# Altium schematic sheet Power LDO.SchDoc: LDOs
size 431 x 279 mm; Date: Not shown in title block; ApprovedBy: Not shown in title block; CheckedBy: Not shown in title block; Author: Not shown in title block; CompanyName: Not shown in title block; Engineer: Not shown in title block; Organization: Not shown in title block; Address1: Not shown in title block; Address2: Not shown in title block; Address3: Not shown in title block; Address4: Not shown in title block; DocumentNumber: 1; Revision: Use project parameter SCH_Rev; SheetNumber: 4; SheetTotal: 15; PageSetup: Record=PageOptions¦CenterHorizontal=True¦CenterVertical=True¦PrintScale=1.00¦XCorrection=1.00¦YCorrection=1.00¦PrintKind=0¦BorderSize=5000000¦LeftOffset=0¦BottomOffset=0¦Orientation=2¦PaperLength=1000¦PaperWidth=1000¦Scale=100¦PaperSource=15¦PrintQuality=600¦MediaType=1¦DitherType=10¦PaperKind=Letter¦PrintScaleMode=1
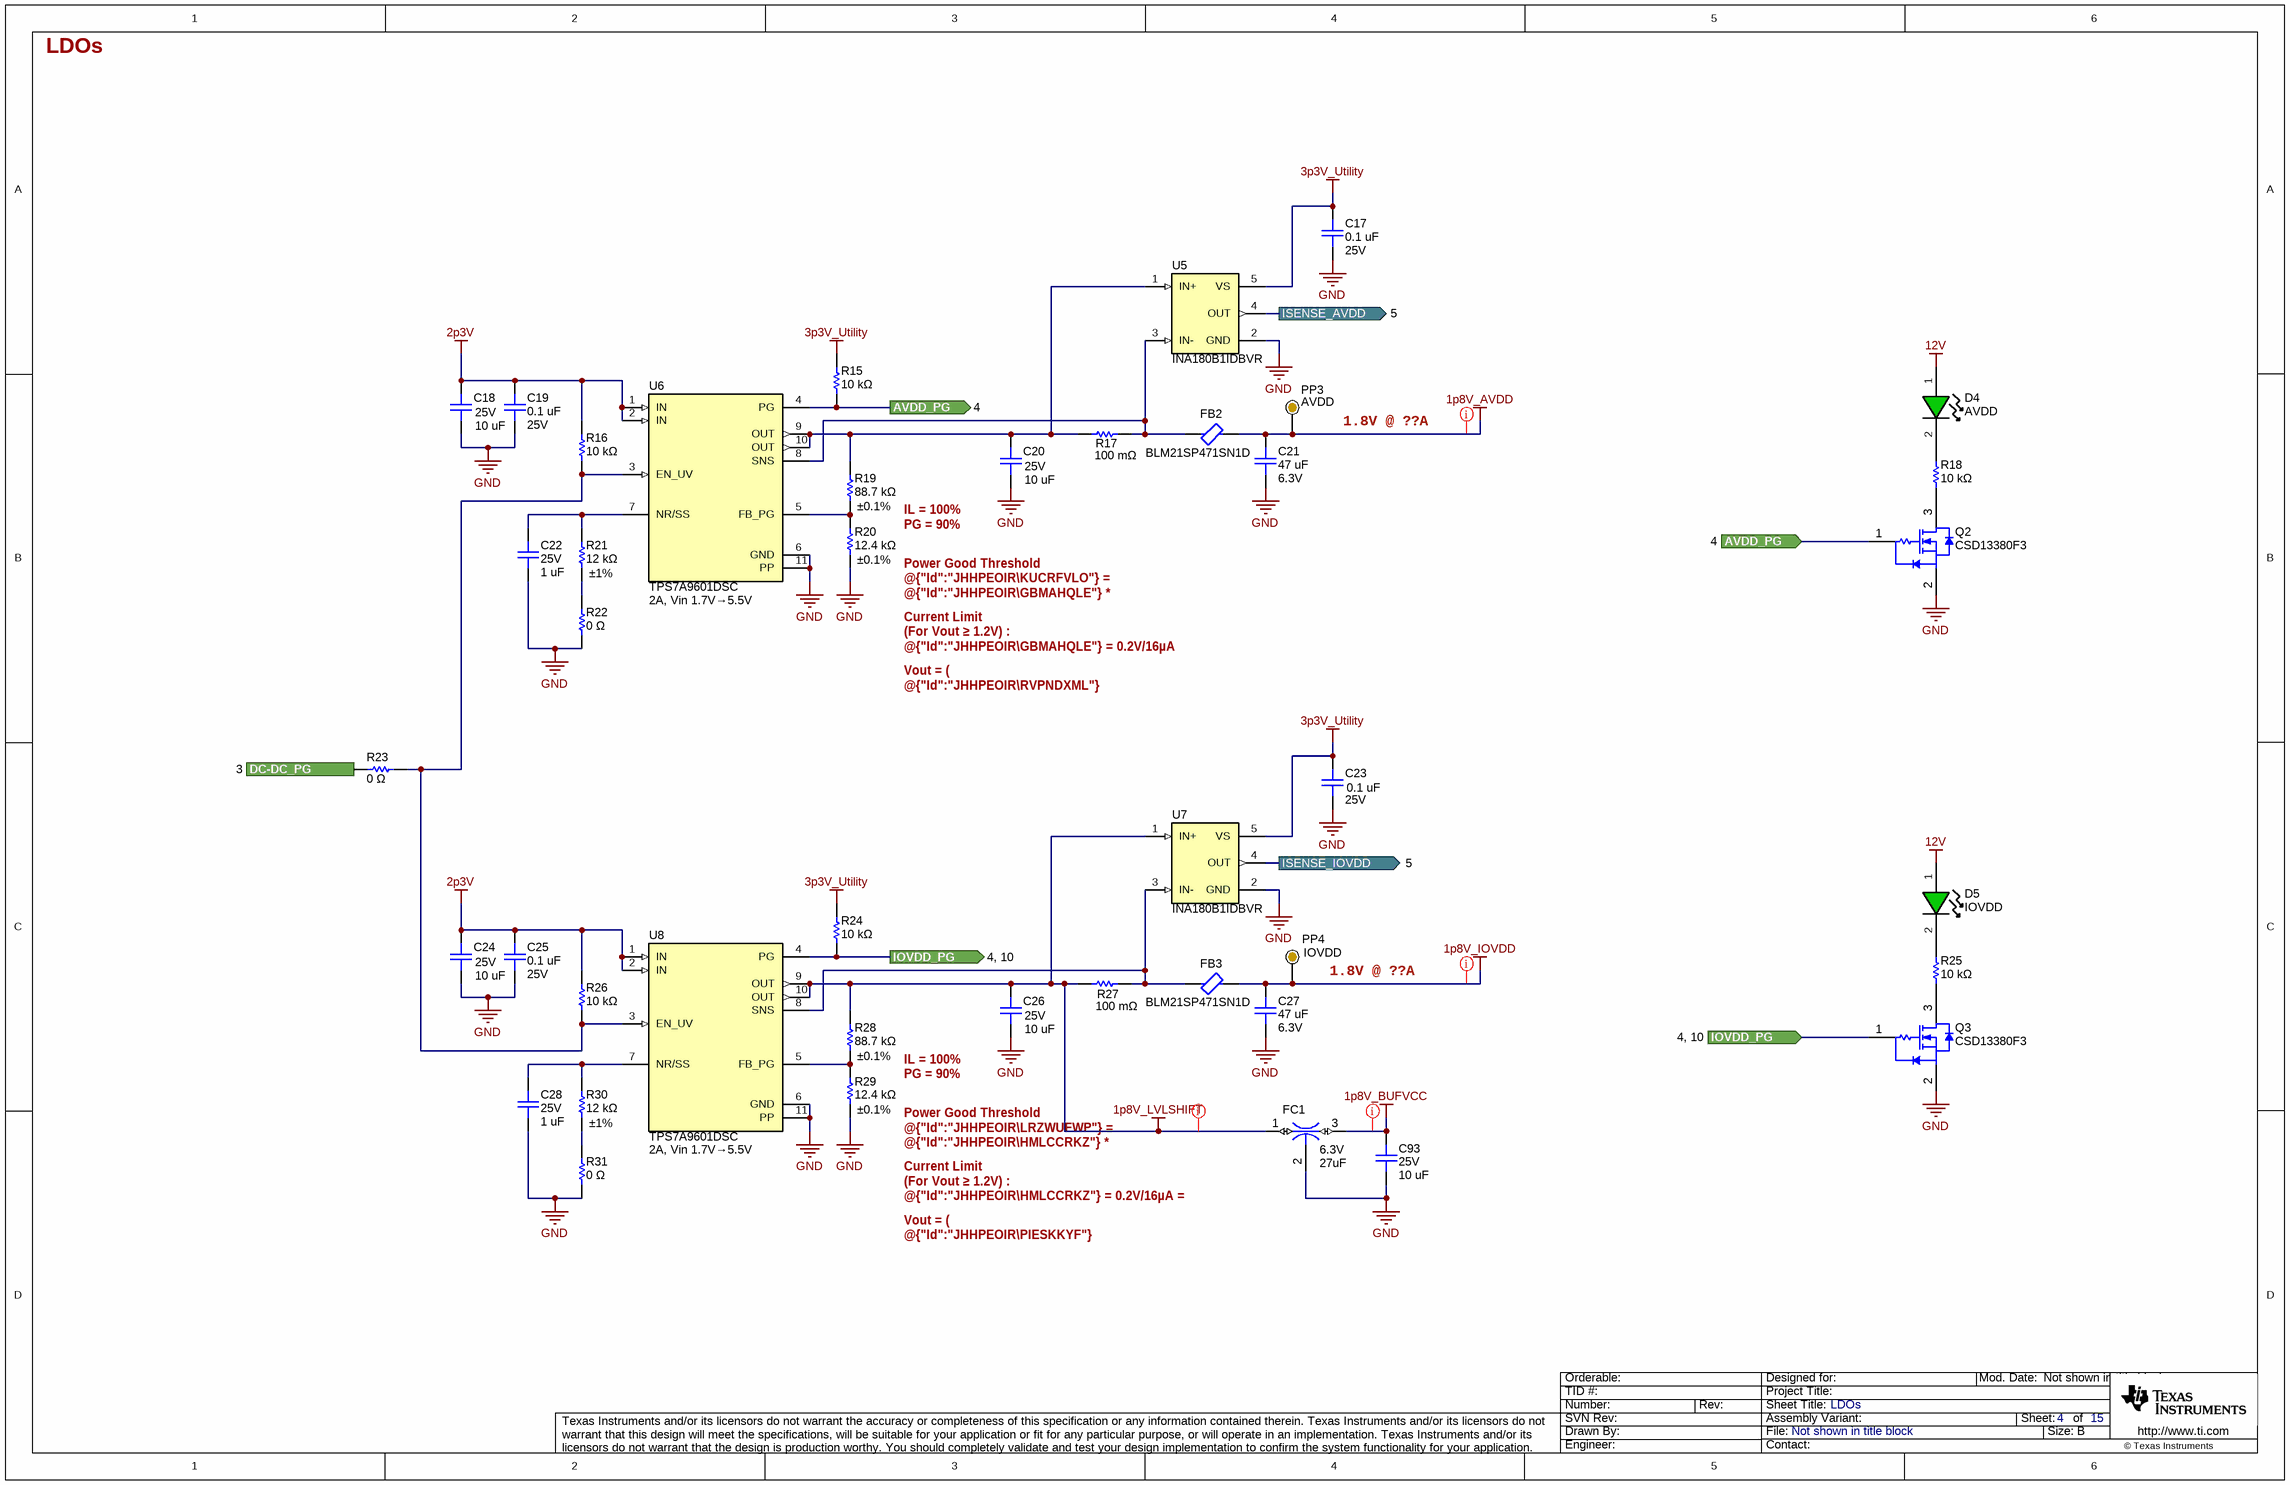
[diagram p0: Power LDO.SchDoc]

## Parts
C17  value 0.1 uF  Voltage - Rated: 25V  [0402L_cap]  (hidden comment: GRT155R71E104KE01J)
C18  value 10 uF  Voltage - Rated: 25V  [0805L_cap]  (hidden comment: C2012X7S1E106K125AC)
C19  value 0.1 uF  Voltage - Rated: 25V  [0402L_cap]  (hidden comment: GRT155R71E104KE01J)
C20  value 10 uF  Voltage - Rated: 25V  [0805L_cap]  (hidden comment: C2012X7S1E106K125AC)
C21  value 47 uF  Voltage - Rated: 6.3V  [0603L_cap]  (hidden comment: GRM188R60J476ME15D)
C22  value 1 uF  Voltage - Rated: 25V  [0402L_cap]  (hidden comment: C1005X5R1E105K050BC)
C23  value 0.1 uF  Voltage - Rated: 25V  [0402L_cap]  (hidden comment: GRT155R71E104KE01J)
C24  value 10 uF  Voltage - Rated: 25V  [0805L_cap]  (hidden comment: C2012X7S1E106K125AC)
C25  value 0.1 uF  Voltage - Rated: 25V  [0402L_cap]  (hidden comment: GRT155R71E104KE01J)
C26  value 10 uF  Voltage - Rated: 25V  [0805L_cap]  (hidden comment: C2012X7S1E106K125AC)
C27  value 47 uF  Voltage - Rated: 6.3V  [0603L_cap]  (hidden comment: GRM188R60J476ME15D)
C28  value 1 uF  Voltage - Rated: 25V  [0402L_cap]  (hidden comment: C1005X5R1E105K050BC)
C93  value 10 uF  Voltage - Rated: 25V  [0603L_cap]  (hidden comment: GRM188R61E106KA73J)
D4  Text1: AVDD  [LED_LTST-C190-Green]  (hidden comment: LTST-C191TGKT)
D5  Text1: IOVDD  [LED_LTST-C190-Green]  (hidden comment: LTST-C191TGKT)
FB2  BLM21SP471SN1D  [0805L]
FB3  BLM21SP471SN1D  [0805L]
FC1  value 27uF  Voltage - Rated: 6.3V  [NFM31PC]  (hidden comment: dcp00001)
PP3  Text1: AVDD  [ProbePoint_TH_40mil]  (hidden comment: Probe Point)  (no BOM)
PP4  Text1: IOVDD  [ProbePoint_TH_40mil]  (hidden comment: Probe Point)  (no BOM)
Q2  CSD13380F3  [YJM0003A]
Q3  CSD13380F3  [YJM0003A]
R15  value 10 kΩ  [0402L]  (hidden comment: ERA-2AEB103X)
R16  value 10 kΩ  [0402L]  (hidden comment: ERJ-2RKF1002X)
R17  value 100 mΩ  [CCS0603FLxLxx]  (hidden comment: WSLP0603R1000FEA)
R18  value 10 kΩ  [0805L]  (hidden comment: ERJ-HP6F1002V)
R19  value 88.7 kΩ  Tolerance: ±0.1%  [0402L]  (hidden comment: RT0402BRD0788K7L)
R20  value 12.4 kΩ  Tolerance: ±0.1%  [0402L]  (hidden comment: ERA-2AEB1242X)
R21  value 12 kΩ  Tolerance: ±1%  [0402L]  (hidden comment: ERJ-2RKF1202X)
R22  value 0 Ω  [0402L]  (hidden comment: ERJ-U020R00X)
R23  value 0 Ω  [0402L]  (hidden comment: ERJ-U020R00X)
R24  value 10 kΩ  [0402L]  (hidden comment: ERA-2AEB103X)
R25  value 10 kΩ  [0805L]  (hidden comment: ERJ-HP6F1002V)
R26  value 10 kΩ  [0402L]  (hidden comment: ERJ-2RKF1002X)
R27  value 100 mΩ  [CCS0603FLxLxx]  (hidden comment: WSLP0603R1000FEA)
R28  value 88.7 kΩ  Tolerance: ±0.1%  [0402L]  (hidden comment: RT0402BRD0788K7L)
R29  value 12.4 kΩ  Tolerance: ±0.1%  [0402L]  (hidden comment: ERA-2AEB1242X)
R30  value 12 kΩ  Tolerance: ±1%  [0402L]  (hidden comment: ERJ-2RKF1202X)
R31  value 0 Ω  [0402L]  (hidden comment: ERJ-U020R00X)
U5  INA180B1IDBVR  [DBV0005A]
U6  TPS7A9601DSC  Text1: 2A, Vin 1.7V→5.5V  [DRC0010J]
U7  INA180B1IDBVR  [DBV0005A]
U8  TPS7A9601DSC  Text1: 2A, Vin 1.7V→5.5V  [DRC0010J]

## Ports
AVDD_PG (in, see 4), AVDD_PG (out, see 4), DC-DC_PG (in, see 3), IOVDD_PG (in, see 4, 10), IOVDD_PG (out, see 4, 10), ISENSE_AVDD (out, see 5), ISENSE_IOVDD (out, see 5)

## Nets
1p8V_AVDD: C21.2 FB2.2 PP3.1
1p8V_BUFVCC: C93.2 FC1.3
1p8V_IOVDD: C27.2 FB3.2 PP4.1
1p8V_LVLSHIFT: C26.2 FC1.1 R27.1 R28.2 U7.1(IN+) U8.9(OUT) U8.10(OUT)
2p3V: C18.2 C19.2 C24.2 C25.2 R16.2 R26.2 U6.1(IN) U6.2(IN) U8.1(IN) U8.2(IN)
3p3V_Utility: C17.2 C23.2 R15.2 R24.2 U5.5(VS) U7.5(VS)
12V: D4.1(A) D5.1(A)
GND: C17.1 C18.1 C19.1 C20.1 C21.1 C22.1 C23.1 C24.1 C25.1 C26.1 C27.1 C28.1 C93.1 FC1.2 Q2.2(S) Q3.2(S) R20.1 R22.1 R29.1 R31.1 U5.2(GND) U6.6(GND) U6.11(PP) U7.2(GND) U8.6(GND) U8.11(PP)
AVDD_PG: Q2.1(G) R15.1 U6.4(PG) ; port AVDD_PG
DC-DC_PG: R23.2 ; port DC-DC_PG
IOVDD_PG: Q3.1(G) R24.1 U8.4(PG) ; port IOVDD_PG
ISENSE_AVDD: U5.4(OUT) ; port ISENSE_AVDD
ISENSE_IOVDD: U7.4(OUT) ; port ISENSE_IOVDD
NetC20_2: C20.2 R17.1 R19.2 U5.1(IN+) U6.9(OUT) U6.10(OUT)
NetC22_2: C22.2 R21.2 U6.7(NR/SS)
NetC28_2: C28.2 R30.2 U8.7(NR/SS)
NetD4_2: D4.2(K) R18.2
NetD5_2: D5.2(K) R25.2
NetFB2_1: FB2.1 R17.2 U5.3(IN-) U6.8(SNS)
NetFB3_1: FB3.1 R27.2 U7.3(IN-) U8.8(SNS)
NetQ2_3: Q2.3(D) R18.1
NetQ3_3: Q3.3(D) R25.1
NetR16_1: R16.1 R23.1 R26.1 U6.3(EN_UV) U8.3(EN_UV)
NetR19_1: R19.1 R20.2 U6.5(FB_PG)
NetR21_1: R21.1 R22.2
NetR28_1: R28.1 R29.2 U8.5(FB_PG)
NetR30_1: R30.1 R31.2

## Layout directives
net class Power; net class DUTPwr: 1p8V_AVDD, 1p8V_IOVDD
net class Power; net class GenPwr: 1p8V_BUFVCC, 1p8V_LVLSHIFT

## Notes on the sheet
- 1.8V @ ??A
- IL = 100%
  PG = 90%
- Power Good Threshold
  @{"Id":"JHHPEOIR\KUCRFVLO"} = @{"Id":"JHHPEOIR\GBMAHQLE"} * (VOUT/0.2*K-1)
  K = PG % Threshold
- Current Limit
  (For Vout ≥ 1.2V) : @{"Id":"JHHPEOIR\GBMAHQLE"} = 0.2V/16µA = 12.4k
- Vout = ( @{"Id":"JHHPEOIR\RVPNDXML"} + @{"Id":"JHHPEOIR\VYCEATNQ"} ) *150µA
  Vout = 1.8V
- (near PP4) 1.8V @ ??A
- Power Good Threshold
  @{"Id":"JHHPEOIR\LRZWUFWP"} = @{"Id":"JHHPEOIR\HMLCCRKZ"} * (VOUT/0.2*K-1)
  K = PG % Threshold
- Current Limit
  (For Vout ≥ 1.2V) : @{"Id":"JHHPEOIR\HMLCCRKZ"} = 0.2V/16µA = 12.4k
- Vout = ( @{"Id":"JHHPEOIR\PIESKKYF"} + @{"Id":"JHHPEOIR\BNWUTHKX"} ) *150µA
  Vout = 1.8V

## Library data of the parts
C17 C19 C23 C25 = capcc09401: CAP CER 0.1UF 25V X7R 0402; Manufacturer: Murata; CompType: Capacitor Ceramic; Tolerance: ±10%; SizeX_mm: 1; SizeY_mm: 0.5; SizeZ_mm: 0.7
C18 C20 C24 C26 = capcc03511: CAP CER 10UF 25V X7S 0805; Manufacturer: TDK Corporation; CompType: Capacitor Ceramic; Tolerance: ±10%; SizeX_mm: 2; SizeY_mm: 1.25; SizeZ_mm: 1.5
C21 C27 = GRM188R60J476ME15D: CAP CER 47UF 6.3V X5R 0603; Manufacturer: Murata; CompType: Capacitor Ceramic; Tolerance: ±20%; SizeX_mm: 1.6; SizeY_mm: 0.81; SizeZ_mm: 0.9
C22 C28 = capcc02750: CAP CER 1UF 25V X5R 0402; Manufacturer: TDK Corporation; CompType: Capacitor Ceramic; Tolerance: ±10%; SizeX_mm: 1; SizeY_mm: 0.5; SizeZ_mm: 0.55
C93 = capcc09400: CAP CER 10UF 25V X5R 0603; Manufacturer: Murata; CompType: Capacitor Ceramic; Tolerance: ±10%; SizeX_mm: 1.6; SizeY_mm: 0.8; SizeZ_mm: 1
D4 D5 = cmp00247: LED GREEN CLEAR CHIP SMD; Manufacturer: Lite-On Inc.; Current Rating (Amps): 20mA; Voltage - Forward (Vf) (Typ): 3.2V; SizeX_mm: 1.6; SizeY_mm: 0.8; SizeZ_mm: 0.65
FB2 FB3 = dcp00579: FERRITEBEAD SMD Z100MHZ=470OHM 2; Manufacturer: Murata Electronics; Current: 2.5A; Impedance: 470 Ω
FC1 = dcp00001: Feed through capactior 27uF; PartNumber: NFM31PC276B0J3L; Manufacturer: Murata; CompType: Feed Thru Cap; Tolerance: ±20%; SizeX_mm: 3.2; SizeY_mm: 1.6; SizeZ_mm: 1.5; Current: 6A; DCR: 5 mΩ
PP3 PP4 = Probe Point: Probe Point that can be used in lue of a test point; UniqueID: cmp00025
Q2 Q3 = CSD13380F3: MOSFET, N-CH, 12 V, 3.6 A, YJM0003A (PICOSTAR-3); Manufacturer: Texas Instruments; CompType: NMOS
R15 R24 = RSMD040200315: RES SMD 10K OHM 0.1% 1/16W 0402; Manufacturer: Panasonic Electronic Components; CompType: Resistor SMD; Power (Watts): 0.063W, 1/16W; Temperature Coefficient: ±25ppm/°C; SizeX_mm: 1; SizeY_mm: 0.5; SizeZ_mm: 0.4
R16 R26 = RSMD040200314: RES SMD 10K OHM 1% 1/10W 0402; Manufacturer: Panasonic Electronic Components; CompType: Resistor SMD; Power (Watts): 0.1W, 1/10W; Temperature Coefficient: ±100ppm/°C; SizeX_mm: 1; SizeY_mm: 0.5; SizeZ_mm: 0.4
R17 R27 = WSLP0603R1000FEA: RES 0.1 OHM 1% 2/5W 0603; Manufacturer: Vishay Dale; CompType: Resistor SMD Sense; Resistance: 3 mΩ; Power (Watts): 0.4W, 2/5W
R18 R25 = RSMD080502076: RES 10K OHM 1% 1/2W 0805; Manufacturer: Panasonic Electronic Components; CompType: Resistor SMD; Power (Watts): 0.5W, 1/2W; Temperature Coefficient: ±100ppm/°C; SizeX_mm: 2; SizeY_mm: 1.25; SizeZ_mm: 0.7
R19 R28 = RSMD040203878: RES SMD 88.7KOHM 0.1% 1/16W 0402; Manufacturer: Yageo; CompType: Resistor SMD; Power (Watts): 0.063W, 1/16W; Temperature Coefficient: ±25ppm/°C; SizeX_mm: 1; SizeY_mm: 0.5; SizeZ_mm: 0.4
R20 R29 = RSMD040200551: RES SMD 12.4KOHM 0.1% 1/16W 0402; Manufacturer: Panasonic Electronic Components; CompType: Resistor SMD; Power (Watts): 0.063W, 1/16W; Temperature Coefficient: ±25ppm/°C; SizeX_mm: 1; SizeY_mm: 0.5; SizeZ_mm: 0.4
R21 R30 = RSMD040200519: RES SMD 12K OHM 1% 1/10W 0402; Manufacturer: Panasonic Electronic Components; CompType: Resistor SMD; Power (Watts): 0.1W, 1/10W; Temperature Coefficient: ±100ppm/°C; SizeX_mm: 1; SizeY_mm: 0.5; SizeZ_mm: 0.4
R22 R23 R31 = RSMD040200004: RES 0 OHM JUMPER 0402 SMD; Manufacturer: Panasonic Electronic Components; CompType: Resistor SMD; Power (Watts): 0.1W, 1/10W; Temperature Coefficient: -100/ +600ppm/°C; SizeX_mm: 1; SizeY_mm: 0.5; SizeZ_mm: 0.4
U5 U7 = INA180B1IDBVR: 26V, 350kHz current sense amplifier; Manufacturer: Texas Instruments; Alt PartNumber: INA180B1IDBVT; CompType: Current Amplifier
U6 U8 = cmp00446: 2-A, ultra-low noise ultra-high PSRR RF voltage regulator; PartNumber: TPS7A9601DSCR; Manufacturer: Texas Instruments; CompType: LDO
